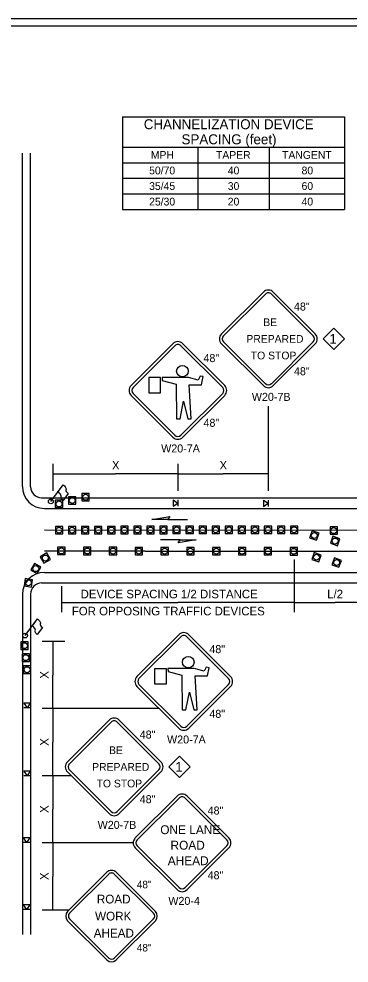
# Model space of a CAD drawing. Extents: x 99988 to 100172, y 99995 to 100047.
# Drawn here: x 100006.94 to 100009.92, y 100001.92 to 100010.44 of the extents above; entities that cross this region are included whole.
import ezdxf

# ---------------------------------------------------------------- set-up
doc = ezdxf.new("R2010")
doc.units = 0
for name, color, linetype in [('Default', 7, 'Continuous'), ('Level 15', 7, 'Continuous'), ('Level 20', 7, 'Continuous'), ('SH_DE_DetailBody1Text', 7, 'Continuous'), ('SH_GI_PlotLimits', 7, 'Continuous'), ('SH_GI_SheetBorder', 7, 'Continuous'), ('SH_GI_TrafficMvmntArrowRt1Lane', 7, 'Continuous'), ('SH_TI_ChanSpacing25to70Note', 7, 'Continuous'), ('SH_TI_SignSpacing35to70Note', 7, 'Continuous'), ('TR_SN_WarningSigns', 7, 'Continuous'), ('TR_WZ_FlaggingStation', 7, 'Continuous'), ('TR_WZ_TrafficSafetyCone', 7, 'Continuous'), ('TR_WZ_WorkZoneDetails', 7, 'Continuous')]:
    doc.layers.add(name, color=color, linetype=linetype)

msp = doc.modelspace()

# ---------------------------------------------------------------- linework, layer by layer
at = {"layer": 'Default'}
for p, q in [((100008.3315, 100006.1011), (100008.3739, 100006.0716)), ((100008.3315, 100006.1011), (100008.3315, 100006.0421)), ((100008.3739, 100006.1011), (100008.3739, 100006.0421)), ((100009.1464, 100006.0986), (100009.1887, 100006.0691)), ((100009.1464, 100006.0986), (100009.1464, 100006.0396)), ((100009.1887, 100006.0986), (100009.1887, 100006.0396)), ((100008.3315, 100006.0421), (100008.3739, 100006.0716)), ((100009.1464, 100006.0396), (100009.1887, 100006.0691)), ((100012.4977, 100005.8223), (100007.1718, 100005.8262)), ((100008.0791, 100005.6372), (100007.1716, 100005.6386)), ((100006.9855, 100004.266), (100007.0151, 100004.2236)), ((100007.0445, 100004.266), (100006.9855, 100004.266)), ((100007.0445, 100004.2236), (100006.9855, 100004.2236)), ((100007.0445, 100004.266), (100007.0151, 100004.2236)), ((100006.9855, 100003.6527), (100007.0151, 100003.6104)), ((100007.0445, 100003.6527), (100006.9855, 100003.6527)), ((100007.0445, 100003.6527), (100007.0151, 100003.6104)), ((100007.0445, 100003.6104), (100006.9855, 100003.6104)), ((100006.9814, 100003.0519), (100007.0109, 100003.0095)), ((100007.0404, 100003.0519), (100006.9814, 100003.0519)), ((100007.0404, 100003.0519), (100007.0109, 100003.0095)), ((100007.0404, 100003.0095), (100006.9814, 100003.0095)), ((100006.9814, 100002.447), (100007.0109, 100002.4046)), ((100007.0404, 100002.447), (100006.9814, 100002.447)), ((100007.0404, 100002.447), (100007.0109, 100002.4046)), ((100007.0404, 100002.4046), (100006.9814, 100002.4046))]:
    msp.add_line(p, q, dxfattribs=at)
at = {"layer": 'Level 15'}
for p, q in [((100007.2516, 100006.3356), (100007.8134, 100006.3356)), ((100008.3752, 100006.3356), (100007.8134, 100006.3356)), ((100008.3752, 100006.3356), (100008.7829, 100006.3356)), ((100009.1906, 100006.3356), (100008.7829, 100006.3356)), ((100007.3248, 100005.1739), (100008.3743, 100005.1739)), ((100009.4237, 100005.1739), (100008.3743, 100005.1739)), ((100009.4237, 100005.1739), (100009.7943, 100005.1739)), ((100010.1648, 100005.1739), (100009.7943, 100005.1739)), ((100007.2475, 100004.8224), (100007.2475, 100004.5199)), ((100007.2475, 100004.2175), (100007.2475, 100004.5199)), ((100007.2475, 100004.2175), (100007.2475, 100003.9148)), ((100007.2475, 100003.6121), (100007.2475, 100003.9148)), ((100007.2475, 100003.6121), (100007.2475, 100003.3094)), ((100007.2475, 100003.0067), (100007.2475, 100003.3094)), ((100007.2475, 100003.0067), (100007.2475, 100002.704)), ((100007.2475, 100002.4013), (100007.2475, 100002.704))]:
    msp.add_line(p, q, dxfattribs=at)
at = {"layer": 'SH_DE_DetailBody1Text'}
for points in [[(100009.7799, 100007.6483), (100009.8765, 100007.5518), (100009.7799, 100007.4553), (100009.6834, 100007.5518)], [(100008.3899, 100003.7888), (100008.4865, 100003.6922), (100008.3899, 100003.5957), (100008.2934, 100003.6922)]]:
    msp.add_lwpolyline(points, close=True, dxfattribs=at)
at = {"layer": 'SH_GI_PlotLimits'}
msp.add_lwpolyline([(99999.3125, 99999.9375), (100015.8125, 99999.9375), (100015.8125, 100010.4375), (99999.3125, 100010.4375)], close=True, dxfattribs=at)
at = {"layer": 'SH_GI_SheetBorder'}
msp.add_line((100000, 100010.375), (100015.75, 100010.375), dxfattribs=at)
at = {"layer": 'SH_GI_TrafficMvmntArrowRt1Lane'}
for p, q in [((100008.2855, 100005.9228), (100008.4623, 100005.9228)), ((100008.3945, 100005.7403), (100008.2177, 100005.7403))]:
    msp.add_line(p, q, dxfattribs=at)
for points in [[(100008.1414, 100005.9228), (100008.3018, 100005.9511), (100008.2855, 100005.9228)], [(100008.5386, 100005.7403), (100008.3782, 100005.712), (100008.3945, 100005.7403)]]:
    msp.add_lwpolyline(points, close=True, dxfattribs=at)
at = {"layer": 'SH_TI_ChanSpacing25to70Note'}
for p, q in [((100007.8758, 100009.2809), (100009.8758, 100009.2809)), ((100008.5584, 100008.7195), (100008.5584, 100009.2809)), ((100009.2005, 100008.7195), (100009.2005, 100009.2809)), ((100007.8758, 100009.1406), (100009.8758, 100009.1406)), ((100007.8758, 100009.0002), (100009.8758, 100009.0002)), ((100007.8758, 100008.8598), (100009.8758, 100008.8598))]:
    msp.add_line(p, q, dxfattribs=at)
at = {"layer": 'SH_TI_SignSpacing35to70Note'}
for p, q in [((100007.8758, 100009.5539), (100007.8758, 100008.7195)), ((100007.8758, 100009.5539), (100009.8758, 100009.5539)), ((100009.8758, 100009.5539), (100009.8758, 100008.7195)), ((100007.8758, 100008.7195), (100009.8758, 100008.7195))]:
    msp.add_line(p, q, dxfattribs=at)
at = {"layer": 'TR_SN_WarningSigns'}
for p, q in [((100008.7688, 100007.5967), (100009.1457, 100007.9736)), ((100009.2355, 100007.9736), (100009.6124, 100007.5967)), ((100008.7867, 100007.5787), (100009.1637, 100007.9557)), ((100009.2175, 100007.9557), (100009.5945, 100007.5787)), ((100007.9534, 100007.1315), (100008.3303, 100007.5085)), ((100007.9713, 100007.1136), (100008.3483, 100007.4905)), ((100008.4021, 100007.4905), (100008.7791, 100007.1136)), ((100008.4201, 100007.5085), (100008.797, 100007.1315)), ((100009.1457, 100007.13), (100008.7688, 100007.5069)), ((100009.1636, 100007.1479), (100008.7867, 100007.5249)), ((100009.5945, 100007.5249), (100009.2175, 100007.1479)), ((100009.6124, 100007.5069), (100009.2354, 100007.13)), ((100008.3303, 100006.6648), (100007.9534, 100007.0418)), ((100008.3483, 100006.6828), (100007.9713, 100007.0597)), ((100008.7791, 100007.0597), (100008.4021, 100006.6828)), ((100008.797, 100007.0418), (100008.4201, 100006.6648)), ((100008.0063, 100004.507), (100008.3833, 100004.8839)), ((100008.0243, 100004.4891), (100008.4012, 100004.866)), ((100008.4551, 100004.866), (100008.832, 100004.4891)), ((100008.473, 100004.8839), (100008.85, 100004.507)), ((100008.3833, 100004.0403), (100008.0063, 100004.4173)), ((100008.4012, 100004.0583), (100008.0243, 100004.4352)), ((100008.832, 100004.4352), (100008.455, 100004.0583)), ((100008.85, 100004.4173), (100008.473, 100004.0403)), ((100007.3788, 100003.7371), (100007.7557, 100004.114)), ((100007.3967, 100003.7192), (100007.7737, 100004.0961)), ((100007.8275, 100004.0961), (100008.2044, 100003.7191)), ((100007.8454, 100004.114), (100008.2224, 100003.7371)), ((100007.7557, 100003.2704), (100007.3788, 100003.6474)), ((100007.7736, 100003.2884), (100007.3967, 100003.6653)), ((100008.2044, 100003.6653), (100007.8275, 100003.2884)), ((100008.2224, 100003.6473), (100007.8454, 100003.2704)), ((100007.9908, 100003.0516), (100008.3677, 100003.4285)), ((100008.0087, 100003.0336), (100008.3857, 100003.4106)), ((100008.4395, 100003.4106), (100008.8165, 100003.0336)), ((100008.4575, 100003.4285), (100008.8344, 100003.0516)), ((100008.3677, 100002.5849), (100007.9908, 100002.9618)), ((100008.3857, 100002.6029), (100008.0087, 100002.9798)), ((100008.8165, 100002.9798), (100008.4395, 100002.6029)), ((100008.8344, 100002.9618), (100008.4575, 100002.5849)), ((100007.3814, 100002.3882), (100007.7348, 100002.7416)), ((100007.3983, 100002.3714), (100007.7517, 100002.7248)), ((100007.8021, 100002.7248), (100008.1555, 100002.3714)), ((100007.819, 100002.7416), (100008.1723, 100002.3882)), ((100007.7348, 100001.9507), (100007.3814, 100002.3041)), ((100007.7516, 100001.9675), (100007.3983, 100002.3209)), ((100008.1555, 100002.3209), (100007.8021, 100001.9675)), ((100008.1723, 100002.3041), (100007.819, 100001.9507))]:
    msp.add_line(p, q, dxfattribs=at)
for points in [[(100008.1127, 100007.2021), (100008.1127, 100007.0649), (100008.2197, 100007.0649), (100008.2197, 100007.2021)], [(100008.2323, 100007.2024), (100008.2339, 100007.1759), (100008.3592, 100007.143), (100008.3619, 100006.8302), (100008.3945, 100006.8302), (100008.4255, 100006.9913), (100008.4646, 100006.8299), (100008.4961, 100006.8299), (100008.4782, 100007.1367), (100008.5894, 100007.1367), (100008.6045, 100007.2112), (100008.5763, 100007.2166), (100008.5582, 100007.1785), (100008.4697, 100007.2024)], [(100008.1656, 100004.5776), (100008.1656, 100004.4404), (100008.2727, 100004.4404), (100008.2727, 100004.5776)], [(100008.2852, 100004.5779), (100008.2868, 100004.5514), (100008.4121, 100004.5185), (100008.4149, 100004.2056), (100008.4474, 100004.2056), (100008.4785, 100004.3668), (100008.5175, 100004.2053), (100008.549, 100004.2053), (100008.5312, 100004.5122), (100008.6423, 100004.5122), (100008.6575, 100004.5867), (100008.6292, 100004.5921), (100008.6111, 100004.554), (100008.5227, 100004.5779)]]:
    msp.add_lwpolyline(points, close=True, dxfattribs=at)
for centre in [(100008.416, 100007.2612), (100008.4689, 100004.6367)]:
    msp.add_circle(centre, 0.0519, dxfattribs=at)
for centre, radius, start, end in [((100009.1906, 100007.9288), 0.0635, 44.99628, 134.99965), ((100009.1906, 100007.9288), 0.0381, 44.99628, 134.99965), ((100008.8136, 100007.5518), 0.0635, 134.99658, 224.99358), ((100008.8136, 100007.5518), 0.0381, 134.99658, 224.99358), ((100009.5675, 100007.5518), 0.0381, 314.99936, 44.99485), ((100009.5675, 100007.5518), 0.0635, 314.99936, 44.99485), ((100008.3752, 100007.4636), 0.0635, 44.99628, 134.99965), ((100008.3752, 100007.4636), 0.0381, 44.99628, 134.99965), ((100007.9982, 100007.0867), 0.0635, 134.99658, 224.99358), ((100007.9982, 100007.0867), 0.0381, 134.99658, 224.99358), ((100008.7521, 100007.0867), 0.0381, 314.99936, 44.99485), ((100008.7521, 100007.0867), 0.0635, 314.99936, 44.99485), ((100009.1906, 100007.1749), 0.0635, 225, 314.99958), ((100009.1906, 100007.1749), 0.0381, 225, 314.99958), ((100008.3752, 100006.7097), 0.0381, 225, 314.99958), ((100008.3752, 100006.7097), 0.0635, 225, 314.99958), ((100008.4281, 100004.8391), 0.0635, 44.99628, 134.99965), ((100008.4281, 100004.8391), 0.0381, 44.99628, 134.99965), ((100008.0512, 100004.4621), 0.0635, 134.99658, 224.99358), ((100008.0512, 100004.4621), 0.0381, 134.99658, 224.99358), ((100008.8051, 100004.4621), 0.0381, 314.99936, 44.99485), ((100008.8051, 100004.4621), 0.0635, 314.99936, 44.99485), ((100007.8006, 100004.0692), 0.0635, 44.99628, 134.99965), ((100007.8006, 100004.0692), 0.0381, 44.99628, 134.99965), ((100008.4281, 100004.0852), 0.0381, 225, 314.99958), ((100008.4281, 100004.0852), 0.0635, 225, 314.99958), ((100007.4236, 100003.6922), 0.0635, 134.99658, 224.99358), ((100007.4236, 100003.6922), 0.0381, 134.99658, 224.99358), ((100008.1775, 100003.6922), 0.0381, 314.99936, 44.99485), ((100008.1775, 100003.6922), 0.0635, 314.99936, 44.99485), ((100008.4126, 100003.3837), 0.0635, 44.99628, 134.99965), ((100008.4126, 100003.3837), 0.0381, 44.99628, 134.99965), ((100007.8006, 100003.3153), 0.0381, 225, 314.99958), ((100007.8006, 100003.3153), 0.0635, 225, 314.99958), ((100008.0357, 100003.0067), 0.0635, 134.99658, 224.99358), ((100008.0357, 100003.0067), 0.0381, 134.99658, 224.99358), ((100008.7896, 100003.0067), 0.0381, 314.99936, 44.99485), ((100008.7896, 100003.0067), 0.0635, 314.99936, 44.99485), ((100007.7769, 100002.6995), 0.0595, 44.99628, 134.99965), ((100007.7769, 100002.6995), 0.0357, 44.99628, 134.99965), ((100008.4126, 100002.6298), 0.0381, 225, 314.99958), ((100008.4126, 100002.6298), 0.0635, 225, 314.99958), ((100007.4235, 100002.3462), 0.0595, 134.99658, 224.99358), ((100007.4235, 100002.3462), 0.0357, 134.99658, 224.99358), ((100008.1303, 100002.3462), 0.0357, 314.99936, 44.99485), ((100008.1303, 100002.3462), 0.0595, 314.99936, 44.99485), ((100007.7769, 100001.9928), 0.0595, 225, 314.99958), ((100007.7769, 100001.9928), 0.0357, 225, 314.99958)]:
    msp.add_arc(centre, radius, start, end, dxfattribs=at)
at = {"layer": 'TR_WZ_FlaggingStation'}
for p, q in [((100007.2301, 100006.0855), (100007.3412, 100006.2355)), ((100007.2961, 100006.1746), (100007.3413, 100006.2357)), ((100007.2961, 100006.1746), (100007.2961, 100006.1746)), ((100007.3863, 100006.158), (100007.34, 100006.0954)), ((100006.9981, 100004.8762), (100007.1091, 100005.0262)), ((100007.064, 100004.9654), (100007.1092, 100005.0264)), ((100007.064, 100004.9654), (100007.064, 100004.9654)), ((100007.1543, 100004.9487), (100007.108, 100004.8861))]:
    msp.add_line(p, q, dxfattribs=at)
for points in [[(100007.34, 100006.0954), (100007.3358, 100006.0989), (100007.3273, 100006.1074), (100007.3218, 100006.1185), (100007.3216, 100006.1267), (100007.3227, 100006.1339), (100007.3211, 100006.1431), (100007.3169, 100006.1503), (100007.3093, 100006.1601), (100007.2961, 100006.1746)], [(100007.3413, 100006.2357), (100007.3441, 100006.233), (100007.3532, 100006.2252), (100007.3597, 100006.2182), (100007.3632, 100006.2116), (100007.3666, 100006.206), (100007.3675, 100006.2003), (100007.3674, 100006.1944), (100007.3656, 100006.1907), (100007.3657, 100006.1836), (100007.3694, 100006.1758), (100007.3748, 100006.1687), (100007.3863, 100006.158)], [(100007.1092, 100005.0264), (100007.1121, 100005.0238), (100007.1211, 100005.0159), (100007.1277, 100005.009), (100007.1312, 100005.0023), (100007.1345, 100004.9968), (100007.1355, 100004.991), (100007.1353, 100004.9851), (100007.1336, 100004.9814), (100007.1336, 100004.9744), (100007.1373, 100004.9666), (100007.1427, 100004.9595), (100007.1543, 100004.9487)], [(100007.108, 100004.8861), (100007.1038, 100004.8896), (100007.0952, 100004.8981), (100007.0897, 100004.9093), (100007.0895, 100004.9175), (100007.0906, 100004.9246), (100007.0891, 100004.9339), (100007.0848, 100004.9411), (100007.0772, 100004.9508), (100007.064, 100004.9654)]]:
    msp.add_lwpolyline(points, dxfattribs=at)
for centre in [(100007.2301, 100006.0855), (100006.9981, 100004.8762)]:
    msp.add_circle(centre, 0.0214, dxfattribs=at)
at = {"layer": 'TR_WZ_TrafficSafetyCone'}
for points in [[(100007.27, 100006.0299), (100007.3368, 100006.0299), (100007.3368, 100006.0967), (100007.27, 100006.0967)], [(100007.3894, 100006.0606), (100007.4562, 100006.0606), (100007.4562, 100006.1274), (100007.3894, 100006.1274)], [(100007.5096, 100006.0899), (100007.5764, 100006.0899), (100007.5764, 100006.1567), (100007.5096, 100006.1567)], [(100007.2709, 100005.7937), (100007.3377, 100005.7937), (100007.3377, 100005.8605), (100007.2709, 100005.8605)], [(100007.3886, 100005.7938), (100007.4554, 100005.7938), (100007.4554, 100005.8606), (100007.3886, 100005.8606)], [(100007.5063, 100005.794), (100007.5731, 100005.794), (100007.5731, 100005.8608), (100007.5063, 100005.8608)], [(100007.624, 100005.7942), (100007.6909, 100005.7942), (100007.6909, 100005.861), (100007.624, 100005.861)], [(100007.7418, 100005.7944), (100007.8086, 100005.7944), (100007.8086, 100005.8612), (100007.7418, 100005.8612)], [(100007.8595, 100005.7946), (100007.9263, 100005.7946), (100007.9263, 100005.8614), (100007.8595, 100005.8614)], [(100007.9772, 100005.7948), (100008.044, 100005.7948), (100008.044, 100005.8616), (100007.9772, 100005.8616)], [(100008.0949, 100005.795), (100008.1617, 100005.795), (100008.1617, 100005.8618), (100008.0949, 100005.8618)], [(100008.2126, 100005.7952), (100008.2794, 100005.7952), (100008.2794, 100005.862), (100008.2126, 100005.862)], [(100008.3303, 100005.7954), (100008.3971, 100005.7954), (100008.3971, 100005.8622), (100008.3303, 100005.8622)], [(100008.448, 100005.7955), (100008.5148, 100005.7955), (100008.5148, 100005.8624), (100008.448, 100005.8624)], [(100008.5657, 100005.7957), (100008.6325, 100005.7957), (100008.6325, 100005.8625), (100008.5657, 100005.8625)], [(100008.6834, 100005.7959), (100008.7502, 100005.7959), (100008.7502, 100005.8627), (100008.6834, 100005.8627)], [(100008.8011, 100005.7961), (100008.868, 100005.7961), (100008.868, 100005.8629), (100008.8011, 100005.8629)], [(100008.9189, 100005.7963), (100008.9857, 100005.7963), (100008.9857, 100005.8631), (100008.9189, 100005.8631)], [(100009.0366, 100005.7965), (100009.1034, 100005.7965), (100009.1034, 100005.8633), (100009.0366, 100005.8633)], [(100009.1543, 100005.7967), (100009.2211, 100005.7967), (100009.2211, 100005.8635), (100009.1543, 100005.8635)], [(100009.272, 100005.7969), (100009.3388, 100005.7969), (100009.3388, 100005.8637), (100009.272, 100005.8637)], [(100009.3897, 100005.7971), (100009.4565, 100005.7971), (100009.4565, 100005.8639), (100009.3897, 100005.8639)], [(100009.7464, 100005.7894), (100009.8132, 100005.7894), (100009.8132, 100005.8562), (100009.7464, 100005.8562)], [(100009.5617, 100005.7586), (100009.6245, 100005.7358), (100009.6473, 100005.7986), (100009.5845, 100005.8214)], [(100009.75, 100005.7087), (100009.8128, 100005.6859), (100009.8356, 100005.7486), (100009.7728, 100005.7715)], [(100007.2914, 100005.606), (100007.3582, 100005.606), (100007.3582, 100005.6728), (100007.2914, 100005.6728)], [(100007.5242, 100005.6056), (100007.591, 100005.6056), (100007.591, 100005.6724), (100007.5242, 100005.6724)], [(100007.7569, 100005.6052), (100007.8237, 100005.6052), (100007.8237, 100005.672), (100007.7569, 100005.672)], [(100007.9897, 100005.6049), (100008.0565, 100005.6049), (100008.0565, 100005.6717), (100007.9897, 100005.6717)], [(100008.2225, 100005.6045), (100008.2893, 100005.6045), (100008.2893, 100005.6713), (100008.2225, 100005.6713)], [(100008.4552, 100005.6041), (100008.522, 100005.6041), (100008.522, 100005.6709), (100008.4552, 100005.6709)], [(100008.688, 100005.6037), (100008.7548, 100005.6037), (100008.7548, 100005.6705), (100008.688, 100005.6705)], [(100008.9208, 100005.6033), (100008.9876, 100005.6033), (100008.9876, 100005.6702), (100008.9208, 100005.6702)], [(100009.1535, 100005.603), (100009.2203, 100005.603), (100009.2203, 100005.6698), (100009.1535, 100005.6698)], [(100009.3863, 100005.6026), (100009.4531, 100005.6026), (100009.4531, 100005.6694), (100009.3863, 100005.6694)], [(100007.1682, 100005.5299), (100007.226, 100005.5633), (100007.1926, 100005.6211), (100007.1348, 100005.5877)], [(100009.5819, 100005.5627), (100009.6447, 100005.5399), (100009.6676, 100005.6027), (100009.6048, 100005.6255)], [(100009.7634, 100005.5147), (100009.8262, 100005.4919), (100009.8491, 100005.5547), (100009.7863, 100005.5775)], [(100007.1066, 100005.4345), (100007.14, 100005.4923), (100007.0821, 100005.5257), (100007.0487, 100005.4679)], [(100007.0542, 100005.3142), (100007.0658, 100005.38), (100007, 100005.3916), (100006.9884, 100005.3258)], [(100006.9587, 100004.752), (100007.0256, 100004.752), (100007.0256, 100004.8188), (100006.9587, 100004.8188)], [(100006.9705, 100004.6436), (100007.0374, 100004.6436), (100007.0374, 100004.7104), (100006.9705, 100004.7104)], [(100006.9823, 100004.5351), (100007.0492, 100004.5351), (100007.0492, 100004.6019), (100006.9823, 100004.6019)]]:
    msp.add_lwpolyline(points, close=True, dxfattribs=at)
for centre in [(100007.3034, 100006.0633), (100007.4228, 100006.094), (100007.543, 100006.1233), (100007.3043, 100005.8271), (100007.422, 100005.8272), (100007.5397, 100005.8274), (100007.6574, 100005.8276), (100007.7752, 100005.8278), (100007.8929, 100005.828), (100008.0106, 100005.8282), (100008.1283, 100005.8284), (100008.246, 100005.8286), (100008.3637, 100005.8288), (100008.4814, 100005.829), (100008.5991, 100005.8291), (100008.7168, 100005.8293), (100008.8346, 100005.8295), (100008.9523, 100005.8297), (100009.07, 100005.8299), (100009.1877, 100005.8301), (100009.3054, 100005.8303), (100009.4231, 100005.8305), (100009.7798, 100005.8228), (100009.6045, 100005.7786), (100009.7928, 100005.7287), (100007.3248, 100005.6394), (100007.5576, 100005.639), (100007.7903, 100005.6386), (100008.0231, 100005.6383), (100008.2559, 100005.6379), (100008.4886, 100005.6375), (100008.7214, 100005.6371), (100008.9542, 100005.6367), (100009.1869, 100005.6364), (100009.4197, 100005.636), (100007.1804, 100005.5755), (100009.6247, 100005.5827), (100007.0944, 100005.4801), (100009.8062, 100005.5347), (100007.0271, 100005.3529), (100006.9922, 100004.7854), (100007.004, 100004.677), (100007.0158, 100004.5685)]:
    msp.add_circle(centre, 0.0268, dxfattribs=at)
at = {"layer": 'TR_WZ_WorkZoneDetails'}
for p, q in [((100006.9735, 100006.2209), (100006.9735, 100009.2274)), ((100007.0478, 100006.2179), (100007.0478, 100009.2274)), ((100009.1906, 100006.1823), (100009.1906, 100006.9464)), ((100007.252, 100006.1807), (100007.2516, 100006.4236)), ((100008.3752, 100006.4236), (100008.3752, 100006.1823)), ((100007.1469, 100006.1188), (100009.3032, 100006.1188)), ((100009.3032, 100006.1188), (100012.4976, 100006.1188)), ((100007.1716, 100006.0227), (100009.3032, 100006.0227)), ((100009.3032, 100006.0227), (100012.4976, 100006.0227)), ((100008.0804, 100005.6386), (100012.4976, 100005.6386)), ((100009.4237, 100005.5629), (100009.4237, 100005.0864)), ((100007.1716, 100005.4465), (100009.3032, 100005.4465)), ((100009.3032, 100005.4465), (100012.4976, 100005.4465)), ((100007.1469, 100005.3505), (100009.3032, 100005.3505)), ((100007.3248, 100005.3232), (100007.3248, 100005.0864)), ((100009.3032, 100005.3505), (100012.4976, 100005.3505)), ((100006.9735, 100005.2483), (100006.9735, 100002.1809)), ((100007.0478, 100005.2514), (100007.0478, 100002.1809)), ((100007.3575, 100004.8224), (100007.1504, 100004.8224)), ((100008.2061, 100004.2175), (100007.1504, 100004.2175)), ((100007.414, 100003.6121), (100007.1504, 100003.6121)), ((100007.9722, 100003.0067), (100007.1504, 100003.0067)), ((100007.3945, 100002.4013), (100007.1504, 100002.4013))]:
    msp.add_line(p, q, dxfattribs=at)
for centre, radius, start, end in [((100007.1717, 100006.2209), 0.1982, 180, 270), ((100007.1469, 100006.2179), 0.0991, 180, 270), ((100007.1717, 100005.2483), 0.1982, 90, 180), ((100007.1469, 100005.2514), 0.0991, 90, 180)]:
    msp.add_arc(centre, radius, start, end, dxfattribs=at)

# ---------------------------------------------------------------- texts
at = {"layer": 'Level 20'}
for s, rotation, p in [('X', 360, (100007.7807, 100006.3741)), ('X', 360, (100008.7502, 100006.3741)), ('DEVICE SPACING 1/2 DISTANCE', 360, (100007.4982, 100005.2124)), ('L/2', 360, (100009.7209, 100005.2124)), ('X', 90, (100007.209, 100004.4872)), ('X', 90, (100007.209, 100003.8821)), ('X', 90, (100007.209, 100003.2767)), ('X', 90, (100007.209, 100002.6713))]:
    msp.add_text(s, height=0.077, rotation=rotation, dxfattribs=at).set_placement(p)
msp.add_text('FOR OPPOSING TRAFFIC DEVICES', height=0.077, dxfattribs=at).set_placement((100007.4192, 100005.0584))
at = {"layer": 'SH_DE_DetailBody1Text'}
for p in [(100009.7414, 100007.5078), (100008.3513, 100003.6482)]:
    msp.add_text('1', height=0.088, dxfattribs=at).set_placement(p)
at = {"layer": 'SH_TI_ChanSpacing25to70Note'}
for s, height, p in [('CHANNELIZATION DEVICE', 0.09, (100008.0678, 100009.4424)), ('SPACING (feet)', 0.09, (100008.4081, 100009.3067)), ('MPH', 0.07, (100008.1315, 100009.1757)), ('TAPER', 0.07, (100008.7187, 100009.1757)), ('TANGENT', 0.07, (100009.3144, 100009.1757)), ('50/70', 0.07, (100008.1162, 100009.0354)), ('40', 0.07, (100008.8249, 100009.0354)), ('80', 0.07, (100009.49, 100009.0354)), ('35/45', 0.07, (100008.1162, 100008.895)), ('30', 0.07, (100008.8249, 100008.895)), ('60', 0.07, (100009.49, 100008.895)), ('25/30', 0.07, (100008.1162, 100008.7547)), ('20', 0.07, (100008.8249, 100008.7547)), ('40', 0.07, (100009.49, 100008.7547))]:
    msp.add_text(s, height=height, dxfattribs=at).set_placement(p)
at = {"layer": 'TR_SN_WarningSigns'}
for s, height, p in [('48"', 0.07219, (100009.4212, 100007.8074)), ('BE', 0.06996, (100009.1448, 100007.6667)), ('PREPARED', 0.06996, (100008.9927, 100007.5168)), ('48"', 0.07219, (100008.6058, 100007.3423)), ('TO STOP', 0.06996, (100009.0325, 100007.3669)), ('48"', 0.07219, (100009.4212, 100007.224)), ('W20-7B', 0.07219, (100009.0419, 100006.9928)), ('48"', 0.07219, (100008.6058, 100006.7589)), ('W20-7A', 0.07219, (100008.2247, 100006.5277)), ('48"', 0.07219, (100008.6588, 100004.7177)), ('48"', 0.07219, (100008.6588, 100004.1344)), ('48"', 0.07219, (100008.0312, 100003.9478)), ('W20-7A', 0.07219, (100008.2776, 100003.9031)), ('BE', 0.06996, (100007.7547, 100003.8072)), ('PREPARED', 0.06996, (100007.6027, 100003.6572)), ('TO STOP', 0.06996, (100007.6425, 100003.5073)), ('48"', 0.07219, (100008.0312, 100003.3645)), ('48"', 0.07219, (100008.6432, 100003.2623)), ('W20-7B', 0.07219, (100007.6519, 100003.1332)), ('ONE LANE', 0.07995, (100008.2165, 100003.0855)), ('ROAD', 0.07995, (100008.3088, 100002.9456)), ('AHEAD', 0.07995, (100008.2839, 100002.8057)), ('48"', 0.07219, (100008.6432, 100002.679)), ('48"', 0.06768, (100008.0047, 100002.5973)), ('ROAD', 0.0787, (100007.6445, 100002.4605)), ('W20-4', 0.07219, (100008.2892, 100002.4477)), ('WORK', 0.0787, (100007.6283, 100002.3068)), ('AHEAD', 0.0787, (100007.6164, 100002.1532)), ('48"', 0.06768, (100008.0047, 100002.0273))]:
    msp.add_text(s, height=height, dxfattribs=at).set_placement(p)

doc.saveas('drawing.dxf')
